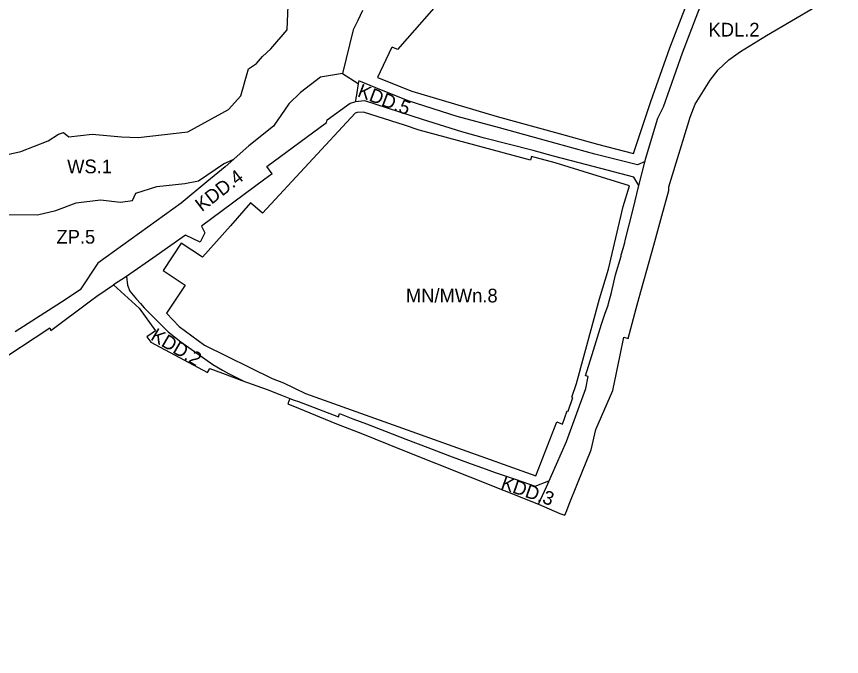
# Model space of a CAD drawing. Extents: x 7427219 to 7428976, y 5542673 to 5543767.
# Drawn here: x 7428025.3 to 7428325.9, y 5542718 to 5542951.2 of the extents above; entities that cross this region are included whole.
import ezdxf

# ---------------------------------------------------------------- set-up
doc = ezdxf.new("R2010")
doc.units = 0
for name, color, linetype in [('linie rozgraniczające', 7, 'Continuous'), ('nieprzekraczalne linie zabudowy', 7, 'Continuous'), ('przeznaczenia terenów', 7, 'Continuous')]:
    doc.layers.add(name, color=color, linetype=linetype)

msp = doc.modelspace()

# ---------------------------------------------------------------- linework, layer by layer
at = {"layer": 'linie rozgraniczające'}
for points in [[(7428254.5, 5542899.22), (7428258.95, 5542914.17), (7428261.03, 5542918.27), (7428267.94, 5542938.04), (7428273.56, 5542952.52), (7428278.76, 5542965.94), (7428281.8, 5542973.5), (7428285.72, 5542983.81), (7428289.48, 5542994.02), (7428293.62, 5543005.28), (7428294.93, 5543012.34), (7428295.4, 5543015.58), (7428297.17, 5543026.12), (7428297.38, 5543030.81), (7428297.72, 5543055.41)], [(7428215.44, 5542773.49), (7428223.26, 5542770.2), (7428225.01, 5542769.57), (7428225.73, 5542771.29), (7428226.66, 5542773.56), (7428229.7, 5542781.04), (7428234.7, 5542793.29), (7428236.31, 5542800.72), (7428242.48, 5542814.94), (7428245.18, 5542827.86), (7428246.55, 5542834.42), (7428248.1, 5542833.92), (7428251.04, 5542844.8), (7428252.14, 5542848.84), (7428256.66, 5542864.93), (7428257.5, 5542867.95), (7428260.43, 5542878.58), (7428262.99, 5542887.82), (7428262.93, 5542889.13), (7428263.79, 5542891.93), (7428269.86, 5542911.75), (7428270.74, 5542914.61), (7428272.59, 5542919.27), (7428277.95, 5542928.06), (7428280.96, 5542931.81), (7428284.81, 5542935.43), (7428289.03, 5542938.46), (7428298.57, 5542944.3), (7428325.85, 5542960.45)], [(7428014.31, 5542899.28), (7428026.79, 5542902.07), (7428036.79, 5542905.9), (7428040.63, 5542908.38), (7428042.43, 5542909.03), (7428044.31, 5542907.36), (7428052.78, 5542908.41), (7428063.53, 5542907.35), (7428069.6, 5542907.18), (7428087.69, 5542909.21), (7428102.46, 5542917.41), (7428107.01, 5542922.33), (7428109.81, 5542932.11), (7428112.7, 5542934.08), (7428114.93, 5542936.68), (7428117.99, 5542939.44), (7428123.94, 5542946.44), (7428124.28, 5542955.21)], [(7428151.39, 5542953.48), (7428149.69, 5542949.76), (7428147.95, 5542946.34), (7428144.05, 5542930.53), (7428149.8, 5542926.81)], [(7428144.05, 5542930.53), (7428136, 5542929.1), (7428128.77, 5542923.59), (7428124.46, 5542919.47), (7428118.91, 5542911.27), (7428109.94, 5542904.1), (7428101.27, 5542896.52), (7428094.59, 5542890.98), (7428085.24, 5542883.18), (7428054.91, 5542861.42), (7428048.48, 5542851.59)], [(7428149.96, 5542927.76), (7428149.8, 5542926.81), (7428149.09, 5542922.66), (7428148.64, 5542920.14)], [(7428254.27, 5542898.43), (7428251.51, 5542897.22), (7428235.96, 5542901.07), (7428221.94, 5542904.94), (7428201.29, 5542910.68), (7428185.84, 5542914.81), (7428167.99, 5542920.47), (7428156.14, 5542925.24), (7428149.96, 5542927.76)], [(7428118.44, 5542893.95), (7428116.5, 5542896.58), (7428138.16, 5542912.58), (7428138.41, 5542913.63), (7428146.89, 5542919.62), (7428148.64, 5542920.14)], [(7428252.03, 5542889.62), (7428250.23, 5542892.67), (7428233.06, 5542897.17), (7428220.86, 5542900.37), (7428213.48, 5542902.37), (7428195.8, 5542906.96), (7428187.55, 5542909.22), (7428173.24, 5542913.67), (7428152.18, 5542920.5), (7428148.64, 5542920.14)], [(7428021.7, 5542879.15), (7428032.91, 5542878.92), (7428039.62, 5542880.49), (7428046.98, 5542883.31), (7428055.91, 5542884.47), (7428063.19, 5542883.59), (7428067.51, 5542884.14), (7428068.73, 5542886.85), (7428076.34, 5542889.34), (7428086.59, 5542890.36), (7428091.56, 5542891.39), (7428100.63, 5542897.6), (7428104.42, 5542899.27)], [(7428252.03, 5542889.62), (7428254.06, 5542897.72), (7428254.5, 5542899.22)], [(7428118.44, 5542893.95), (7428115.7, 5542891.93), (7428092.62, 5542874.89), (7428093.9, 5542872.46), (7428092.21, 5542868.98), (7428086.85, 5542871.58), (7428076.12, 5542864.06), (7428065.38, 5542856.54), (7428060.65, 5542853.48)], [(7428218.31, 5542779.92), (7428225.63, 5542796.36), (7428232.69, 5542815.74), (7428233.51, 5542820.11), (7428232.61, 5542820.27), (7428235.52, 5542829.72), (7428238.43, 5542839.17), (7428239.68, 5542842.82), (7428240.82, 5542846.11), (7428240.97, 5542846.67), (7428242.02, 5542850.7), (7428243.57, 5542857.06), (7428245.55, 5542863.95), (7428245.58, 5542864.4), (7428246.25, 5542866.67), (7428246.91, 5542868.89), (7428247.08, 5542869.57), (7428249.9, 5542880.98), (7428252.03, 5542889.62)], [(7428065.38, 5542856.54), (7428065.66, 5542853.39), (7428066.58, 5542851.11), (7428067.82, 5542849.67), (7428069.05, 5542848.23), (7428070.44, 5542846.64), (7428071.83, 5542845.05), (7428080.49, 5542836.33), (7428085.2, 5542832.71), (7428091.03, 5542828.57), (7428096.85, 5542824.44), (7428100.31, 5542822.43), (7428102.56, 5542821.19), (7428105.67, 5542819.58), (7428107.1, 5542818.87), (7428108.39, 5542818.24)], [(7428048.48, 5542851.59), (7428041.66, 5542847.1), (7428024.83, 5542836.36)], [(7428052.28, 5542847.66), (7428054.55, 5542849.35), (7428060.65, 5542853.48)], [(7428060.65, 5542853.48), (7428069.94, 5542844.97), (7428075.89, 5542836.65), (7428074.71, 5542835.87)], [(7427924.47, 5542718.04), (7427930.66, 5542739.04), (7427934.16, 5542751.15), (7427946.59, 5542766.83), (7427954.44, 5542777), (7427964.36, 5542790.19), (7427968.41, 5542794.33), (7427981.32, 5542801.92), (7427985.74, 5542804.52), (7428000.42, 5542812.87), (7428016.3, 5542823.99), (7428037.38, 5542837.79), (7428037.77, 5542836.88), (7428052.28, 5542847.66)], [(7428074.71, 5542835.87), (7428072.74, 5542834.57), (7428074.23, 5542832.53), (7428094.83, 5542821.56), (7428095.73, 5542823), (7428100.37, 5542821.25)], [(7428100.37, 5542821.25), (7428107.31, 5542818.63), (7428116.57, 5542815.31), (7428121.78, 5542813.23)], [(7428121.78, 5542813.23), (7428124.81, 5542812.02), (7428124.1, 5542810.16), (7428128.07, 5542808.52), (7428141.81, 5542802.83), (7428151.38, 5542799.15), (7428165.39, 5542793.48), (7428215.44, 5542773.49)], [(7428124.81, 5542812.02), (7428126.42, 5542811.48), (7428128.03, 5542810.94), (7428135.31, 5542808.14), (7428142.6, 5542805.35), (7428142.73, 5542805.77), (7428142.97, 5542806.54), (7428147.86, 5542804.66), (7428152.74, 5542802.79), (7428159.95, 5542800.02), (7428167.15, 5542797.25), (7428175.09, 5542794.2), (7428183.04, 5542791.15), (7428190.5, 5542788.36), (7428195.09, 5542786.73), (7428199.68, 5542785.09), (7428206.93, 5542782.6), (7428214.19, 5542780.11), (7428219.24, 5542782.01)], [(7428215.44, 5542773.49), (7428218.31, 5542779.92)]]:
    msp.add_lwpolyline(points, dxfattribs=at)
at = {"layer": 'nieprzekraczalne linie zabudowy'}
for points in [[(7428187.03, 5542965.44), (7428164.07, 5542939.25), (7428163.8, 5542939.37), (7428162.08, 5542940.09), (7428161.92, 5542939.87), (7428156.8, 5542929.04), (7428169.26, 5542924.02), (7428200.4, 5542914.82), (7428222.94, 5542908.57), (7428236.92, 5542904.71), (7428250.06, 5542901.32), (7428256.42, 5542920.23), (7428263.25, 5542939.77), (7428268.9, 5542954.33)], [(7428148.65, 5542915.97), (7428114.85, 5542879.57), (7428110.57, 5542883.36), (7428103.19, 5542874.99), (7428093.07, 5542863.51), (7428085.32, 5542868.65), (7428078.7, 5542858.67), (7428086.7, 5542853.36), (7428079.93, 5542843.16), (7428084.5, 5542838.29), (7428093.8, 5542831.51), (7428118.47, 5542819.28), (7428122.55, 5542817.7), (7428130.6, 5542813.82), (7428214.48, 5542783.87), (7428222.11, 5542803.5), (7428224.26, 5542802.75), (7428225.94, 5542807.57), (7428226.28, 5542807.46), (7428228.01, 5542812.44), (7428227.62, 5542812.58), (7428229.32, 5542817.46), (7428237.68, 5542848.32), (7428240.93, 5542859.19), (7428246.32, 5542882.03), (7428248.65, 5542889.52), (7428221.53, 5542897.97), (7428212.9, 5542900.27), (7428212.48, 5542898.9), (7428172.02, 5542909.8), (7428166.62, 5542911.61), (7428151.75, 5542916.43), (7428149.42, 5542916.2), (7428148.65, 5542915.97)]]:
    msp.add_lwpolyline(points, dxfattribs=at)

# ---------------------------------------------------------------- texts
at = {"layer": 'przeznaczenia terenów'}
for s, p in [('KDL.2', (7428277.4, 5542943.94)), ('WS.1', (7428043.72, 5542894.11)), ('ZP.5', (7428039.83, 5542868.48)), ('MN/MWn.8', (7428167.15, 5542847.06))]:
    msp.add_text(s, height=5, dxfattribs=at).set_placement(p)
for s, rotation, p in [('KDD.5', 339.1939, (7428149.19, 5542922.22)), ('KDD.4', 37.4272, (7428092.79, 5542879.9)), ('KDD.2', 329.4545, (7428073.81, 5542833.67)), ('KDD.3', 340.9872, (7428201.42, 5542779.28))]:
    msp.add_text(s, height=5, rotation=rotation, dxfattribs=at).set_placement(p)

doc.saveas('drawing.dxf')
